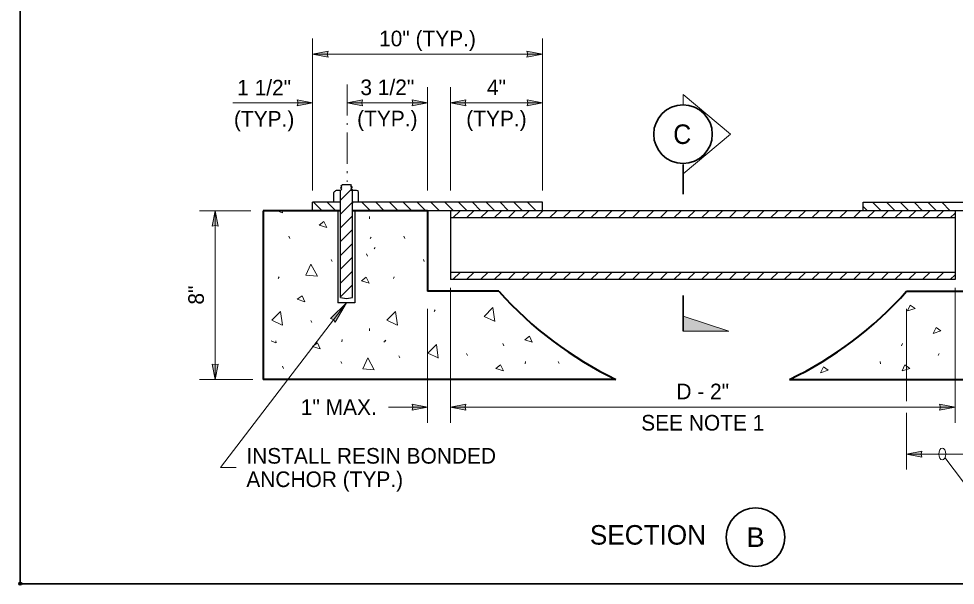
# Model space of a CAD drawing. Extents: x 99860 to 103153, y 99998 to 102077.
# Drawn here: x 99860 to 100819, y 99998 to 100578 of the extents above; entities that cross this region are included whole.
import ezdxf
from ezdxf.enums import TextEntityAlignment as Align

# ---------------------------------------------------------------- set-up
doc = ezdxf.new("R2010")
doc.units = 0
doc.header["$LTSCALE"] = 6.4
doc.header["$PDMODE"] = 32
doc.header["$PDSIZE"] = 3.2
doc.linetypes.add('DOT_DASHED', pattern=[7.7, 5, -1.2, 0.3, -1.2])
for name, color, linetype, lineweight in [('1', 7, 'Continuous', 13), ('13', 7, 'Continuous', 40), ('15', 7, 'Continuous', 13), ('17', 7, 'Continuous', 13), ('18', 7, 'Continuous', 13), ('20', 7, 'Continuous', 13), ('9', 7, 'Continuous', 13)]:
    doc.layers.add(name, color=color, linetype=linetype, lineweight=lineweight)
doc.layers.add('60', color=7, linetype='Continuous')

msp = doc.modelspace()

# ---------------------------------------------------------------- hatches: boundary and pattern name
at = {"layer": '15'}
for points in [[(100161.322, 100541.884), (100177.047, 100538.8), (100176.319, 100541.884), (100177.047, 100544.968)], [(100396.482, 100541.884), (100380.757, 100538.8), (100381.485, 100541.884), (100380.757, 100544.968)], [(100161.322, 100491.884), (100145.597, 100488.8), (100146.325, 100491.884), (100145.597, 100494.968)], [(100196.612, 100491.884), (100212.337, 100488.8), (100211.609, 100491.884), (100212.337, 100494.968)], [(100278.932, 100491.884), (100263.207, 100488.8), (100263.935, 100491.884), (100263.207, 100494.968)], [(100302.462, 100491.884), (100318.187, 100488.8), (100317.459, 100491.884), (100318.187, 100494.968)], [(100396.552, 100491.884), (100380.827, 100488.8), (100381.555, 100491.884), (100380.827, 100494.968)], [(100061.397, 100381.515), (100064.481, 100365.79), (100061.397, 100366.518), (100058.313, 100365.79)], [(100195.859, 100287.304), (100184.389, 100267.342), (100182.657, 100269.993), (100179.642, 100270.962)], [(100061.397, 100208.705), (100058.313, 100224.43), (100061.397, 100223.702), (100064.481, 100224.43)], [(100278.942, 100180.375), (100263.217, 100177.291), (100263.945, 100180.375), (100263.217, 100183.459)], [(100302.462, 100180.375), (100318.187, 100177.291), (100317.459, 100180.375), (100318.187, 100183.459)], [(100818.982, 100180.375), (100803.257, 100177.291), (100803.985, 100180.375), (100803.257, 100183.459)], [(100769.422, 100132.309), (100785.147, 100129.225), (100784.419, 100132.309), (100785.147, 100135.393)]]:
    msp.add_hatch(color=256, dxfattribs=at).paths.add_polyline_path(points)
at = {"layer": '9'}
msp.add_hatch(color=256, dxfattribs=at).paths.add_polyline_path([(100540.513, 100273.615), (100587.395, 100258.09), (100540.513, 100258.09)])

# ---------------------------------------------------------------- linework, layer by layer
at = {"layer": '1', "lineweight": 25}
for p, q in [((100189.942, 100402.125), (100185.302, 100402.125)), ((100189.692, 100292.698), (100189.692, 100402.125)), ((100189.942, 100402.125), (100189.732, 100402.335)), ((100191.872, 100408.355), (100200.042, 100408.215)), ((100200.042, 100408.215), (100200.732, 100407.455)), ((100200.732, 100407.455), (100200.042, 100406.975)), ((100206.192, 100402.125), (100200.417, 100402.125)), ((100208.202, 100390.295), (100208.202, 100401.015)), ((100183.092, 100390.295), (100183.092, 100400.125)), ((100161.322, 100381.515), (100161.322, 100390.295)), ((100189.692, 100390.295), (100161.322, 100390.295)), ((100187.038, 100381.459), (100187.038, 100287.305)), ((100189.692, 100381.515), (100189.692, 100390.295)), ((100396.552, 100390.295), (100201.972, 100390.295)), ((100204.678, 100381.459), (100204.678, 100287.305)), ((100842.502, 100381.515), (100278.942, 100381.515)), ((100302.462, 100381.515), (100302.462, 100310.945)), ((100396.552, 100381.515), (100396.552, 100390.295)), ((100724.892, 100381.515), (100724.892, 100390.295)), ((100724.892, 100390.295), (100919.472, 100390.295)), ((100818.982, 100381.515), (100818.982, 100310.945)), ((100818.982, 100374.105), (100302.462, 100374.105)), ((100818.982, 100318.275), (100302.462, 100318.275)), ((100818.982, 100310.945), (100302.462, 100310.945)), ((100204.678, 100287.305), (100187.038, 100287.305))]:
    msp.add_line(p, q, dxfattribs=at)
at = {"layer": '1', "lineweight": 35}
msp.add_lwpolyline([(99862, 99999.5), (103151, 99999.5), (103151, 102075.5), (99862, 102075.5)], close=True, dxfattribs=at)
at = {"layer": '1', "lineweight": 25}
for points in [[(100189.692, 100292.698), (100195.832, 100291.734), (100201.972, 100292.698), (100201.972, 100402.125)], [(100189.732, 100402.335), (100191.322, 100403.515), (100189.802, 100404.965), (100191.182, 100405.865), (100190.072, 100406.975), (100191.872, 100408.355)], [(100200.042, 100406.975), (100201.972, 100405.455), (100200.452, 100404.615), (100201.972, 100403.165), (100200.417, 100402.125)]]:
    msp.add_lwpolyline(points, dxfattribs=at)
for centre, radius, start, end in [((100186.752, 100398.222), 4.132, 110.20557, 152.52832), ((100206.211, 100399.771), 2.325, 32.69635, 91.70415)]:
    msp.add_arc(centre, radius, start, end, dxfattribs=at)
at = {"layer": '13'}
for p, q in [((100110.717, 100381.515), (100110.717, 100208.705)), ((100189.692, 100381.515), (100110.717, 100381.515)), ((100278.942, 100381.515), (100201.972, 100381.515)), ((100278.942, 100381.515), (100278.942, 100298.945)), ((100352.022, 100298.945), (100278.942, 100298.945)), ((100769.422, 100298.945), (100842.502, 100298.945)), ((100471.792, 100208.705), (100110.717, 100208.705)), ((100649.652, 100208.705), (101010.727, 100208.705))]:
    msp.add_line(p, q, dxfattribs=at)
for centre, start, end in [((100638.774, 100554.933), 221.7557, 244.2524), ((100482.67, 100554.933), 295.7476, 318.2443)]:
    msp.add_arc(centre, 384.391, start, end, dxfattribs=at)
at = {"layer": '15'}
for p, q in [((100161.322, 100557.884), (100161.322, 100402.282)), ((100396.552, 100557.884), (100396.552, 100402.282)), ((100396.482, 100541.884), (100161.322, 100541.884)), ((100278.932, 100507.872), (100278.932, 100402.282)), ((100302.462, 100507.872), (100302.462, 100402.282)), ((100079.705, 100491.884), (100161.322, 100491.884)), ((100278.932, 100491.884), (100196.612, 100491.884)), ((100396.552, 100491.884), (100302.462, 100491.884)), ((100045.397, 100381.515), (100098.067, 100381.515)), ((100061.397, 100208.705), (100061.397, 100381.515)), ((100302.462, 100302.644), (100302.462, 100164.375)), ((100818.982, 100302.644), (100818.982, 100164.375)), ((100195.858, 100287.305), (100067.105, 100118.467)), ((100278.942, 100281.159), (100278.942, 100164.375)), ((100769.422, 100281.159), (100769.422, 100186.375)), ((100045.397, 100208.705), (100100.207, 100208.705)), ((100238.952, 100180.375), (100278.942, 100180.375)), ((100302.462, 100180.375), (100818.982, 100180.375)), ((100769.422, 100174.375), (100769.422, 100116.309)), ((100842.502, 100132.309), (100769.422, 100132.309)), ((100808.716, 100128.67), (100837.27, 100090.939)), ((100067.105, 100118.467), (100083.105, 100118.467))]:
    msp.add_line(p, q, dxfattribs=at)
at = {"layer": '15', "linetype": 'DOT_DASHED'}
msp.add_line((100196.612, 100510.908), (100196.612, 100411.055), dxfattribs=at)
at = {"layer": '15'}
for points in [[(100161.322, 100541.884), (100177.047, 100538.8), (100176.319, 100541.884), (100177.047, 100544.968)], [(100396.482, 100541.884), (100380.757, 100538.8), (100381.485, 100541.884), (100380.757, 100544.968)], [(100161.322, 100491.884), (100145.597, 100488.8), (100146.325, 100491.884), (100145.597, 100494.968)], [(100196.612, 100491.884), (100212.337, 100488.8), (100211.609, 100491.884), (100212.337, 100494.968)], [(100278.932, 100491.884), (100263.207, 100488.8), (100263.935, 100491.884), (100263.207, 100494.968)], [(100302.462, 100491.884), (100318.187, 100488.8), (100317.459, 100491.884), (100318.187, 100494.968)], [(100396.552, 100491.884), (100380.827, 100488.8), (100381.555, 100491.884), (100380.827, 100494.968)], [(100061.397, 100381.515), (100064.481, 100365.79), (100061.397, 100366.518), (100058.313, 100365.79)], [(100195.859, 100287.304), (100184.389, 100267.342), (100182.657, 100269.993), (100179.642, 100270.962)], [(100061.397, 100208.705), (100058.313, 100224.43), (100061.397, 100223.702), (100064.481, 100224.43)], [(100278.942, 100180.375), (100263.217, 100177.291), (100263.945, 100180.375), (100263.217, 100183.459)], [(100302.462, 100180.375), (100318.187, 100177.291), (100317.459, 100180.375), (100318.187, 100183.459)], [(100818.982, 100180.375), (100803.257, 100177.291), (100803.985, 100180.375), (100803.257, 100183.459)], [(100769.422, 100132.309), (100785.147, 100129.225), (100784.419, 100132.309), (100785.147, 100135.393)]]:
    msp.add_lwpolyline(points, close=True, dxfattribs=at)
msp.add_ellipse((100805.962, 100132.309), major_axis=(0, -6), ratio=0.57735, dxfattribs=at)
at = {"layer": '17'}
for p, q in [((100125.422, 100381.515), (100130.192, 100379.295)), ((100130.472, 100379.225), (100130.122, 100381.515)), ((100219.642, 100375.565), (100219.372, 100373.345)), ((100138.012, 100353.215), (100136.972, 100355.425)), ((100221.102, 100354.395), (100220.132, 100352.935)), ((100255.692, 100353.215), (100254.722, 100355.425)), ((100225.322, 100343.875), (100224.352, 100342.425)), ((100217.362, 100335.015), (100216.392, 100337.235)), ((100181.382, 100329.345), (100180.422, 100331.555)), ((100275.612, 100329.345), (100274.642, 100331.555)), ((100127.152, 100313.645), (100126.172, 100312.185)), ((100244.902, 100313.645), (100243.932, 100312.185)), ((100286.669, 100279.864), (100285.709, 100278.404)), ((100160.362, 100266.945), (100159.382, 100269.155)), ((100219.642, 100260.785), (100219.372, 100258.575)), ((100119.012, 100248.376), (100123.792, 100246.156)), ((100123.992, 100246.086), (100123.652, 100248.376)), ((100191.54, 100249.509), (100191.32, 100247.289)), ((100235.205, 100248.34), (100234.245, 100246.88)), ((100236.175, 100248.89), (100235.205, 100247.44)), ((100357.169, 100243.264), (100356.199, 100245.474)), ((100764.276, 100243.264), (100765.246, 100245.474)), ((100250.705, 100230.69), (100249.665, 100232.91)), ((100319.809, 100233.164), (100318.839, 100235.374)), ((100801.636, 100233.164), (100802.606, 100235.374)), ((100131.542, 100220.076), (100130.572, 100222.286)), ((100191.205, 100225.02), (100190.235, 100227.23)), ((100379.109, 100227.004), (100378.889, 100224.794)), ((100413.636, 100225), (100412.666, 100227.21)), ((100742.336, 100227.004), (100742.556, 100224.794))]:
    msp.add_line(p, q, dxfattribs=at)
for points in [[(100175.777, 100364.154), (100172.797, 100370.304), (100167.887, 100366.574)], [(100219.092, 100307.275), (100216.112, 100313.365), (100211.212, 100309.695)], [(100153.454, 100288.347), (100150.544, 100294.437), (100145.634, 100290.767)], [(100770.26, 100278.814), (100773.16, 100284.904), (100778.08, 100281.234)], [(100796.716, 100255.924), (100799.696, 100262.014), (100804.606, 100258.344)], [(100386.21, 100247), (100383.31, 100253.09), (100378.39, 100249.42)], [(100169.12, 100239.959), (100166.21, 100246.119), (100161.3, 100242.379)], [(100356.689, 100217.454), (100353.779, 100223.544), (100348.869, 100219.874)], [(100681.29, 100215.62), (100684.27, 100221.77), (100689.18, 100218.04)], [(100764.756, 100217.454), (100767.666, 100223.544), (100772.576, 100219.874)]]:
    msp.add_lwpolyline(points, close=True, dxfattribs=at)
for points in [[(100166.266, 100314.358), (100159.626, 100326.888), (100154.436, 100315.398), (100165.986, 100314.358)], [(100130.472, 100264.385), (100128.532, 100278.425), (100119.672, 100269.365), (100130.192, 100264.455)], [(100248.152, 100264.385), (100246.212, 100278.425), (100237.432, 100269.365), (100247.942, 100264.455)], [(100347.704, 100268.194), (100345.774, 100282.234), (100336.984, 100273.174), (100347.504, 100268.264)], [(100289.919, 100230.604), (100287.989, 100244.644), (100279.199, 100235.584), (100289.719, 100230.674)], [(100224.345, 100218.38), (100217.705, 100230.9), (100212.585, 100219.42), (100224.135, 100218.38)]]:
    msp.add_lwpolyline(points, dxfattribs=at)
at = {"layer": '18'}
for p, q in [((100201.271, 100403.833), (100189.692, 100392.254)), ((100170.984, 100381.515), (100162.204, 100390.295)), ((100185.126, 100381.515), (100176.346, 100390.295)), ((100201.972, 100390.392), (100189.692, 100378.112)), ((100201.972, 100389.315), (100202.952, 100390.295)), ((100220.504, 100381.515), (100211.724, 100390.295)), ((100234.647, 100381.515), (100225.867, 100390.295)), ((100248.789, 100381.515), (100240.009, 100390.295)), ((100262.931, 100381.515), (100254.151, 100390.295)), ((100277.073, 100381.515), (100268.293, 100390.295)), ((100291.215, 100381.515), (100282.435, 100390.295)), ((100305.357, 100381.515), (100296.577, 100390.295)), ((100312.224, 100381.515), (100304.814, 100374.105)), ((100319.499, 100381.515), (100310.719, 100390.295)), ((100326.366, 100381.515), (100318.956, 100374.105)), ((100333.642, 100381.515), (100324.862, 100390.295)), ((100340.508, 100381.515), (100333.098, 100374.105)), ((100347.784, 100381.515), (100339.004, 100390.295)), ((100354.65, 100381.515), (100347.24, 100374.105)), ((100361.926, 100381.515), (100353.146, 100390.295)), ((100368.792, 100381.515), (100361.382, 100374.105)), ((100376.068, 100381.515), (100367.288, 100390.295)), ((100382.934, 100381.515), (100375.524, 100374.105)), ((100390.21, 100381.515), (100381.43, 100390.295)), ((100397.076, 100381.515), (100389.666, 100374.105)), ((100411.219, 100381.515), (100403.809, 100374.105)), ((100425.361, 100381.515), (100417.951, 100374.105)), ((100439.503, 100381.515), (100432.093, 100374.105)), ((100453.645, 100381.515), (100446.235, 100374.105)), ((100467.787, 100381.515), (100460.377, 100374.105)), ((100481.929, 100381.515), (100474.519, 100374.105)), ((100496.071, 100381.515), (100488.661, 100374.105)), ((100510.214, 100381.515), (100502.804, 100374.105)), ((100524.356, 100381.515), (100516.946, 100374.105)), ((100538.498, 100381.515), (100531.088, 100374.105)), ((100552.64, 100381.515), (100545.23, 100374.105)), ((100566.782, 100381.515), (100559.372, 100374.105)), ((100580.924, 100381.515), (100573.514, 100374.105)), ((100595.066, 100381.515), (100587.656, 100374.105)), ((100609.208, 100381.515), (100601.798, 100374.105)), ((100623.351, 100381.515), (100615.941, 100374.105)), ((100637.493, 100381.515), (100630.083, 100374.105)), ((100651.635, 100381.515), (100644.225, 100374.105)), ((100665.777, 100381.515), (100658.367, 100374.105)), ((100679.919, 100381.515), (100672.509, 100374.105)), ((100694.061, 100381.515), (100686.651, 100374.105)), ((100708.203, 100381.515), (100700.793, 100374.105)), ((100722.346, 100381.515), (100714.936, 100374.105)), ((100729.282, 100381.515), (100724.892, 100385.905)), ((100736.488, 100381.515), (100729.078, 100374.105)), ((100743.424, 100381.515), (100734.644, 100390.295)), ((100750.63, 100381.515), (100743.22, 100374.105)), ((100757.566, 100381.515), (100748.786, 100390.295)), ((100764.772, 100381.515), (100757.362, 100374.105)), ((100771.709, 100381.515), (100762.929, 100390.295)), ((100778.914, 100381.515), (100771.504, 100374.105)), ((100785.851, 100381.515), (100777.071, 100390.295)), ((100793.056, 100381.515), (100785.646, 100374.105)), ((100799.993, 100381.515), (100791.213, 100390.295)), ((100807.198, 100381.515), (100799.788, 100374.105)), ((100814.135, 100381.515), (100805.355, 100390.295)), ((100201.972, 100376.25), (100189.692, 100363.97)), ((100818.982, 100379.157), (100813.931, 100374.105)), ((100201.972, 100362.108), (100189.692, 100349.828)), ((100201.972, 100347.966), (100189.692, 100335.685)), ((100201.972, 100333.823), (100189.692, 100321.543)), ((100201.972, 100319.681), (100189.692, 100307.401)), ((100312.224, 100318.355), (100304.814, 100310.945)), ((100326.366, 100318.355), (100318.956, 100310.945)), ((100340.508, 100318.355), (100333.098, 100310.945)), ((100354.65, 100318.355), (100347.24, 100310.945)), ((100368.792, 100318.355), (100361.382, 100310.945)), ((100382.934, 100318.355), (100375.524, 100310.945)), ((100397.076, 100318.355), (100389.666, 100310.945)), ((100411.219, 100318.355), (100403.809, 100310.945)), ((100425.361, 100318.355), (100417.951, 100310.945)), ((100439.503, 100318.355), (100432.093, 100310.945)), ((100453.645, 100318.355), (100446.235, 100310.945)), ((100467.787, 100318.355), (100460.377, 100310.945)), ((100481.929, 100318.355), (100474.519, 100310.945)), ((100496.071, 100318.355), (100488.661, 100310.945)), ((100510.214, 100318.355), (100502.804, 100310.945)), ((100524.356, 100318.355), (100516.946, 100310.945)), ((100538.498, 100318.355), (100531.088, 100310.945)), ((100552.64, 100318.355), (100545.23, 100310.945)), ((100566.782, 100318.355), (100559.372, 100310.945)), ((100580.924, 100318.355), (100573.514, 100310.945)), ((100595.066, 100318.355), (100587.656, 100310.945)), ((100609.208, 100318.355), (100601.798, 100310.945)), ((100623.351, 100318.355), (100615.941, 100310.945)), ((100637.493, 100318.355), (100630.083, 100310.945)), ((100651.635, 100318.355), (100644.225, 100310.945)), ((100665.777, 100318.355), (100658.367, 100310.945)), ((100679.919, 100318.355), (100672.509, 100310.945)), ((100694.061, 100318.355), (100686.651, 100310.945)), ((100708.203, 100318.355), (100700.793, 100310.945)), ((100722.346, 100318.355), (100714.936, 100310.945)), ((100736.488, 100318.355), (100729.078, 100310.945)), ((100750.63, 100318.355), (100743.22, 100310.945)), ((100764.772, 100318.355), (100757.362, 100310.945)), ((100778.914, 100318.355), (100771.504, 100310.945)), ((100793.056, 100318.355), (100785.646, 100310.945)), ((100807.198, 100318.355), (100799.788, 100310.945)), ((100818.982, 100315.997), (100813.931, 100310.945)), ((100201.972, 100305.539), (100189.692, 100293.259))]:
    msp.add_line(p, q, dxfattribs=at)
at = {"layer": '20', "lineweight": 35}
msp.add_circle((100540.512, 100459.898), 30, dxfattribs=at)
at = {"layer": '60'}
msp.add_point((99862, 99999.5), dxfattribs=at)
at = {"layer": '9'}
msp.add_line((100540.511, 100419.296), (100540.511, 100429.898), dxfattribs=at)
at = {"layer": '9', "lineweight": 35}
for p, q in [((100540.512, 100428.335), (100540.512, 100398.335)), ((100540.512, 100294.615), (100540.512, 100258.091))]:
    msp.add_line(p, q, dxfattribs=at)
at = {"layer": '9'}
msp.add_lwpolyline([(100540.511, 100489.897), (100540.511, 100500.499), (100588.975, 100459.898), (100540.511, 100419.296)], dxfattribs=at)
msp.add_lwpolyline([(100540.513, 100273.615), (100587.395, 100258.09), (100540.513, 100258.09)], close=True, dxfattribs=at)
at = {"layer": '9', "lineweight": 35}
msp.add_circle((100614.738, 100047.153), 30, dxfattribs=at)
at = {"layer": '9'}
msp.add_arc((100540.512, 100459.898), 30, 269.99779, 90.00221, dxfattribs=at)

# ---------------------------------------------------------------- texts
at = {"layer": '20'}
for s, p in [('10" (TYP.)', (100278.903, 100549.884)), ('1 1/2"', (100111.651, 100499.542)), ('3 1/2"', (100237.773, 100499.884)), ('4"', (100349.509, 100499.884)), ('(TYP.)', (100111.65, 100467.542)), ('(TYP.)', (100237.774, 100467.884)), ('(TYP.)', (100349.509, 100467.884)), ('D - 2"', (100560.724, 100188.375)), ('SEE NOTE 1', (100560.724, 100156.375))]:
    msp.add_text(s, height=16, dxfattribs=at).set_placement(p, align=Align.CENTER)
for s, width, p in [('C', 0.95, (100539.678, 100449.879)), ('B', 1.05, (100614.739, 100037.153))]:
    msp.add_text(s, height=20, dxfattribs=dict(at, width=width)).set_placement(p, align=Align.CENTER)
msp.add_text('8"', height=16, rotation=90, dxfattribs=at).set_placement((100049.952, 100295.112), align=Align.CENTER)
for s, p in [('1" MAX.', (100149.2, 100172.375)), ('INSTALL RESIN BONDED', (100093.425, 100122.467)), ('ANCHOR (TYP.)', (100093.425, 100098.467))]:
    msp.add_text(s, height=16, dxfattribs=at).set_placement(p)
msp.add_text('SECTION', height=20, dxfattribs=at).set_placement((100564.036, 100039.535), align=Align.RIGHT)

doc.saveas('drawing.dxf')
